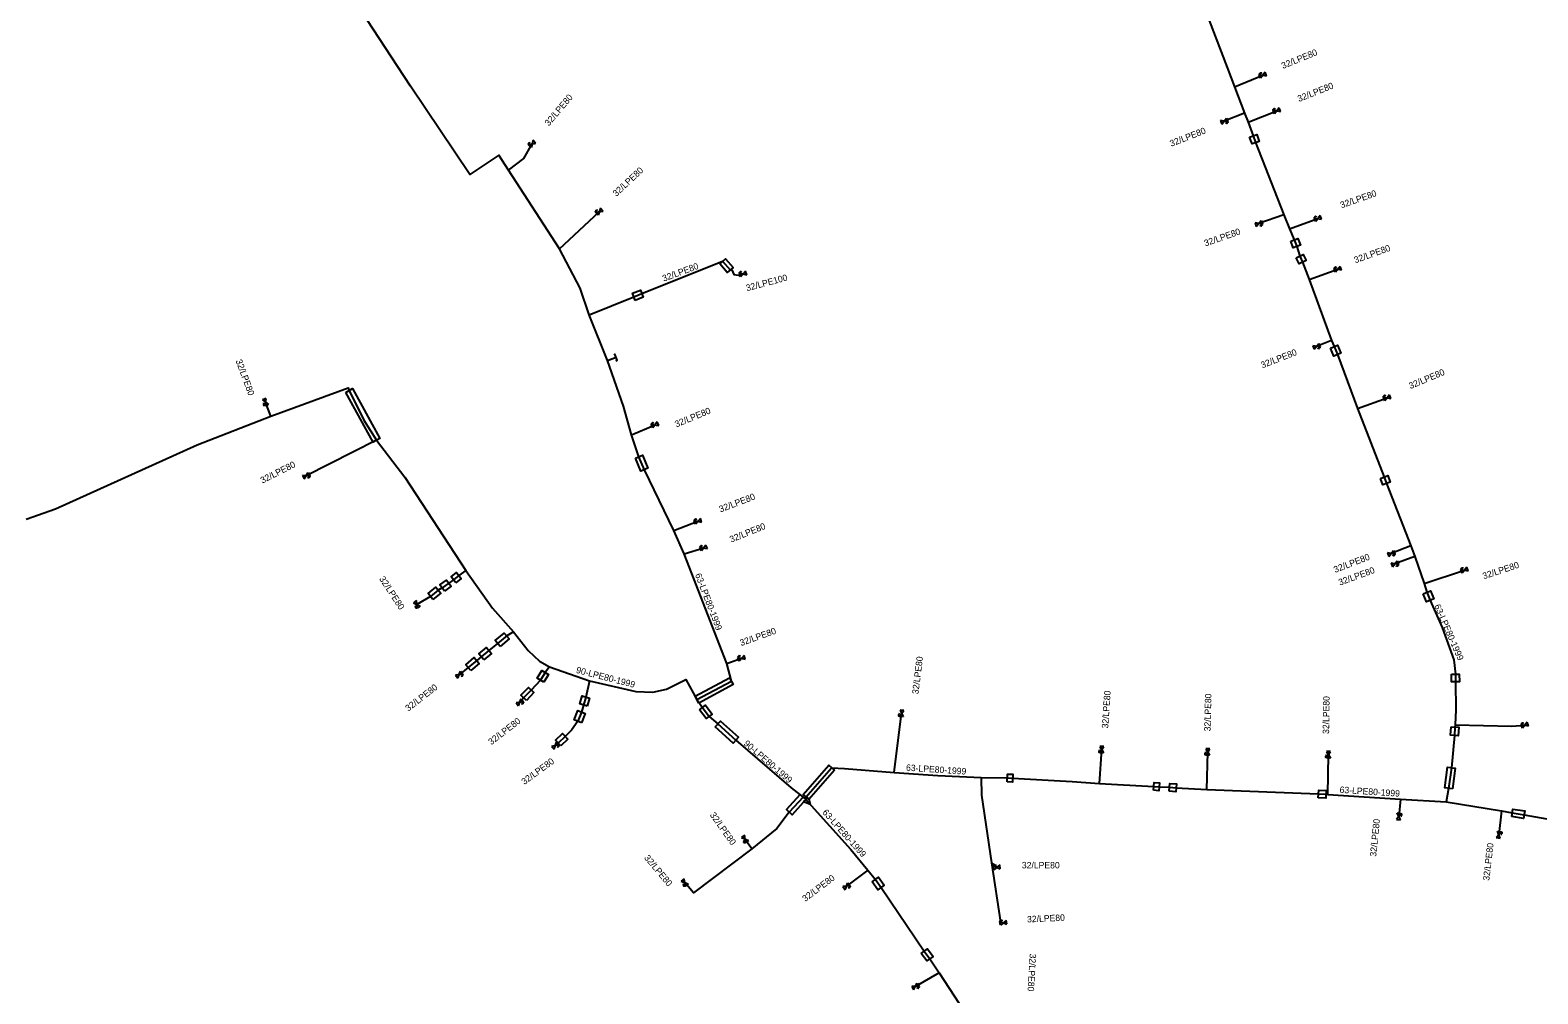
# Model space of a CAD drawing. Extents: x -762927 to -761200, y -1154354 to -1152015.
# Drawn here: x -761676.6 to -761442.6, y -1152557.7 to -1152408 of the extents above; entities that cross this region are included whole.
import ezdxf

# ---------------------------------------------------------------- set-up
doc = ezdxf.new("R2010")
doc.units = 0
for name, color, linetype in [('Vrstva 1', 7, 'Continuous'), ('Vrstva 21', 7, 'Continuous'), ('Vrstva 26', 7, 'Continuous'), ('Vrstva 29', 7, 'Continuous'), ('Vrstva 31', 7, 'Continuous'), ('Vrstva 32', 7, 'Continuous'), ('Vrstva 33', 7, 'Continuous')]:
    doc.layers.add(name, color=color, linetype=linetype)

# ---------------------------------------------------------------- blocks, each defined once
blk = doc.blocks.new('DEC122')
at = {"layer": 'Vrstva 1'}
for p, q in [((-0.5, 0.5), (0.5, 0)), ((-0.5, -0.5), (-0.5, 0.5)), ((0.5, 0), (-0.5, -0.5))]:
    blk.add_line(p, q, dxfattribs=at)
blk = doc.blocks.new('DEC063-SN')
at = {"layer": 'Vrstva 1'}
for p, q in [((-0.5, -0.3), (0.5, 0.3)), ((0.5, -0.3), (-0.5, 0.3)), ((-0.5, 0.3), (-0.5, -0.3)), ((0.5, 0.3), (0.5, -0.3)), ((0.126, -0.318), (0.126, -0.458)), ((0.126, -0.384), (0.206, -0.384)), ((0.206, -0.458), (0.206, -0.318)), ((0.366, -0.458), (0.366, -0.318))]:
    blk.add_line(p, q, dxfattribs=at)
for points in [[(0.246, -0.318), (0.246, -0.418), (0.252, -0.438), (0.264, -0.451), (0.281, -0.458), (0.292, -0.458), (0.309, -0.451), (0.321, -0.438), (0.326, -0.418), (0.326, -0.318)], [(0.366, -0.318), (0.418, -0.318), (0.435, -0.325), (0.441, -0.331), (0.446, -0.344), (0.446, -0.364), (0.441, -0.378), (0.435, -0.384), (0.418, -0.391), (0.366, -0.391)]]:
    blk.add_lwpolyline(points, dxfattribs=at)
blk = doc.blocks.new('DEC130-SN')
at = {"layer": 'Vrstva 1'}
blk.add_lwpolyline([(0.2, 0.5), (0, 0.5), (0, -0.5), (0.2, -0.5)], dxfattribs=at)

msp = doc.modelspace()

# ---------------------------------------------------------------- linework, layer by layer
at = {"layer": 'Vrstva 21'}
for points in [[(-761494.58, -1152404.14), (-761490.85, -1152413.85), (-761489.7, -1152416.84), (-761488.16, -1152420.95), (-761487.6, -1152422.35), (-761486.8, -1152424.45), (-761486.42, -1152425.51), (-761482.06, -1152436.72), (-761481.18, -1152438.87), (-761480.42, -1152440.61), (-761480.05, -1152441.63), (-761479.58, -1152443.13), (-761479.14, -1152444.06), (-761478.09, -1152446.77), (-761474.65, -1152456.23), (-761474.25, -1152457.19), (-761473.73, -1152458.42), (-761470.62, -1152466.8), (-761466.48, -1152477.43), (-761466.1, -1152478.45), (-761462.35, -1152488.13), (-761461.73, -1152489.79), (-761460.26, -1152493.95), (-761459.84, -1152495.33), (-761459.33, -1152496.58), (-761457.49, -1152500.82), (-761455.66, -1152505.82), (-761455.42, -1152508.04), (-761455.4, -1152509.24), (-761455.33, -1152513.56), (-761455.47, -1152515.91), (-761455.49, -1152516.25), (-761455.58, -1152517.56), (-761456.03, -1152522.58), (-761456.47, -1152525.78), (-761456.83, -1152527.87)], [(-761573.13, -1152512), (-761567.78, -1152509.12), (-761568.47, -1152506.37), (-761575.11, -1152489.35), (-761576.69, -1152485.72), (-761581.29, -1152476.29), (-761582.13, -1152474.29), (-761583.3, -1152470.86), (-761584.55, -1152466.45), (-761587.02, -1152459.35), (-761589.85, -1152452.27), (-761591.23, -1152448.11), (-761594.46, -1152442.02), (-761602.36, -1152429.8), (-761603.86, -1152427.44), (-761608.36, -1152430.48), (-761617.59, -1152416.73), (-761625.33, -1152404.89)], [(-761677.24, -1152483.96), (-761672.69, -1152482.38), (-761650.69, -1152472.45), (-761639.27, -1152467.98), (-761627.28, -1152463.58), (-761627.11, -1152464), (-761624.85, -1152468.58), (-761622.86, -1152471.73), (-761618.45, -1152477.46), (-761609.01, -1152491.92), (-761604.85, -1152497.81), (-761601.61, -1152501.48), (-761599.32, -1152504.35), (-761597.57, -1152506.03), (-761596.02, -1152506.9), (-761589.78, -1152509.1), (-761582.63, -1152510.73), (-761579.95, -1152510.84), (-761577.86, -1152510.36), (-761574.83, -1152508.85), (-761573.13, -1152512)], [(-761573.13, -1152512), (-761572.26, -1152513.22), (-761571.23, -1152514.59), (-761569.89, -1152515.77), (-761567.09, -1152518.29), (-761558.48, -1152525.68), (-761556.66, -1152527.12), (-761556.37, -1152527.31)], [(-761556.37, -1152527.31), (-761556.21, -1152527.12), (-761552.23, -1152522.56), (-761550.25, -1152522.69), (-761542.52, -1152523.31), (-761535.75, -1152523.8), (-761529, -1152524.1), (-761524.95, -1152524.15), (-761524.13, -1152524.19), (-761514.88, -1152524.71), (-761510.67, -1152525.03), (-761502.21, -1152525.46), (-761501.38, -1152525.53), (-761499.78, -1152525.61), (-761498.74, -1152525.69), (-761493.99, -1152525.96), (-761476.66, -1152526.63), (-761475.5, -1152526.68), (-761475.2, -1152526.7), (-761463.93, -1152527.44), (-761456.83, -1152527.87)], [(-761556.37, -1152527.31), (-761555.86, -1152527.89)], [(-761555.86, -1152527.89), (-761549.23, -1152535.25), (-761546.63, -1152538.48), (-761545.44, -1152539.91), (-761544.54, -1152541.17), (-761537.84, -1152551.04), (-761536.98, -1152552.22), (-761535.54, -1152554.43), (-761529.45, -1152563.76), (-761525.2, -1152570.86), (-761520.77, -1152578.65), (-761517.06, -1152586.65), (-761515.83, -1152589.42), (-761514.08, -1152593.75), (-761509.53, -1152605.92), (-761503.36, -1152620.97), (-761502.33, -1152623.3), (-761499.83, -1152629.35)], [(-761456.83, -1152527.87), (-761448.25, -1152529.25), (-761446.58, -1152529.57), (-761444.73, -1152529.87), (-761425.09, -1152533.35), (-761412.86, -1152535.83), (-761404.73, -1152537.14), (-761396.67, -1152538.6), (-761395, -1152538.89), (-761392.98, -1152539.26), (-761384.89, -1152540.72), (-761378.87, -1152541.76), (-761369.46, -1152544.68), (-761366.06, -1152546), (-761363.94, -1152546.96), (-761363.78, -1152547.02), (-761358.42, -1152549.62), (-761356.97, -1152550.5), (-761355.51, -1152551.26), (-761353.56, -1152552.55), (-761349.19, -1152555.34), (-761336.19, -1152563.79)]]:
    msp.add_lwpolyline(points, dxfattribs=at)
at = {"layer": 'Vrstva 29'}
for points in [[(-761487.36, -1152424.65), (-761486.23, -1152424.25), (-761485.85, -1152425.31), (-761486.98, -1152425.71)], [(-761480.98, -1152440.81), (-761479.85, -1152440.41), (-761479.48, -1152441.43), (-761480.61, -1152441.83)], [(-761569.6, -1152444.31), (-761568.68, -1152443.53), (-761567.53, -1152444.89), (-761568.45, -1152445.67)], [(-761480.12, -1152443.39), (-761479.04, -1152442.87), (-761478.6, -1152443.8), (-761479.68, -1152444.32)], [(-761582.69, -1152450.01), (-761583.13, -1152448.89), (-761581.91, -1152448.4), (-761581.47, -1152449.52)], [(-761474.8, -1152457.42), (-761473.7, -1152456.96), (-761473.18, -1152458.19), (-761474.28, -1152458.65)], [(-761627.64, -1152464.29), (-761626.58, -1152463.71), (-761622.33, -1152471.44), (-761623.39, -1152472.02)], [(-761582.68, -1152474.52), (-761581.58, -1152474.06), (-761580.74, -1152476.06), (-761581.84, -1152476.52)], [(-761467.04, -1152477.64), (-761465.92, -1152477.22), (-761465.54, -1152478.24), (-761466.66, -1152478.66)], [(-761610.54, -1152493.85), (-761611.28, -1152492.91), (-761610.44, -1152492.24), (-761609.7, -1152493.18)], [(-761614.1, -1152496.46), (-761614.86, -1152495.53), (-761613.66, -1152494.55), (-761612.9, -1152495.48)], [(-761612.29, -1152495.14), (-761613.01, -1152494.18), (-761611.98, -1152493.42), (-761611.26, -1152494.38)], [(-761460.4, -1152495.56), (-761459.28, -1152495.1), (-761458.77, -1152496.35), (-761459.89, -1152496.81)], [(-761603.68, -1152503.73), (-761604.44, -1152502.81), (-761603.03, -1152501.65), (-761602.27, -1152502.57)], [(-761606.2, -1152505.82), (-761606.98, -1152504.9), (-761605.81, -1152503.91), (-761605.03, -1152504.83)], [(-761608.22, -1152507.48), (-761609, -1152506.57), (-761607.7, -1152505.46), (-761606.92, -1152506.36)], [(-761596.9, -1152509.28), (-761597.92, -1152508.66), (-761597.2, -1152507.48), (-761596.18, -1152508.1)], [(-761572.84, -1152512.53), (-761573.41, -1152511.47), (-761568.06, -1152508.59), (-761567.49, -1152509.65)], [(-761456.02, -1152508.05), (-761454.82, -1152508.03), (-761454.8, -1152509.23), (-761456, -1152509.25)], [(-761599.59, -1152512.14), (-761600.46, -1152511.32), (-761599.29, -1152510.09), (-761598.43, -1152510.91)], [(-761590.17, -1152513.01), (-761591.31, -1152512.65), (-761590.93, -1152511.41), (-761589.79, -1152511.77)], [(-761591.06, -1152515.58), (-761592.18, -1152515.14), (-761591.6, -1152513.7), (-761590.48, -1152514.14)], [(-761572.74, -1152513.58), (-761571.78, -1152512.86), (-761570.75, -1152514.23), (-761571.71, -1152514.95)], [(-761570.29, -1152516.22), (-761569.49, -1152515.32), (-761566.69, -1152517.84), (-761567.49, -1152518.74)], [(-761456.09, -1152516.21), (-761454.89, -1152516.29), (-761454.98, -1152517.6), (-761456.18, -1152517.52)], [(-761594.27, -1152519.18), (-761595.09, -1152518.31), (-761593.99, -1152517.27), (-761593.17, -1152518.13)], [(-761555.76, -1152527.51), (-761556.66, -1152526.73), (-761552.68, -1152522.17), (-761551.78, -1152522.95)], [(-761524.98, -1152524.75), (-761524.92, -1152523.55), (-761524.1, -1152523.59), (-761524.16, -1152524.79)], [(-761455.88, -1152525.86), (-761457.06, -1152525.7), (-761456.62, -1152522.5), (-761455.44, -1152522.66)], [(-761502.26, -1152526.06), (-761502.16, -1152524.86), (-761501.33, -1152524.93), (-761501.43, -1152526.13)], [(-761499.83, -1152526.21), (-761499.73, -1152525.01), (-761498.69, -1152525.09), (-761498.79, -1152526.29)], [(-761476.69, -1152527.23), (-761476.63, -1152526.03), (-761475.47, -1152526.08), (-761475.53, -1152527.28)], [(-761557.1, -1152526.72), (-761556.22, -1152527.52), (-761558.36, -1152529.86), (-761559.24, -1152529.05)], [(-761446.68, -1152530.16), (-761446.48, -1152528.98), (-761444.63, -1152529.28), (-761444.83, -1152530.46)], [(-761545.93, -1152540.26), (-761544.95, -1152539.56), (-761544.05, -1152540.82), (-761545.03, -1152541.52)], [(-761538.32, -1152551.39), (-761537.35, -1152550.69), (-761536.49, -1152551.87), (-761537.46, -1152552.57)]]:
    msp.add_lwpolyline(points, close=True, dxfattribs=at)
at = {"layer": 'Vrstva 31'}
for points in [[(-761489.7, -1152416.84), (-761489.69, -1152416.83), (-761485.28, -1152415.03)], [(-761487.6, -1152422.35), (-761483.14, -1152420.58)], [(-761488.16, -1152420.95), (-761491.3, -1152422.17)], [(-761602.36, -1152429.8), (-761599.99, -1152427.96), (-761598.71, -1152425.71)], [(-761594.46, -1152442.02), (-761588.28, -1152436.23)], [(-761482.06, -1152436.72), (-761485.94, -1152438.07)], [(-761481.18, -1152438.87), (-761476.75, -1152437.31)], [(-761589.85, -1152452.27), (-761582.91, -1152449.45), (-761581.69, -1152448.96), (-761569.14, -1152443.92), (-761567.99, -1152445.28), (-761567.7, -1152445.24)], [(-761567.7, -1152445.24), (-761567.41, -1152445.99), (-761566.68, -1152446.09), (-761565.97, -1152445.9)], [(-761478.09, -1152446.77), (-761473.65, -1152445.18)], [(-761474.65, -1152456.23), (-761476.99, -1152457.14)], [(-761587.02, -1152459.35), (-761585.68, -1152458.84)], [(-761470.62, -1152466.8), (-761466.02, -1152465.12)], [(-761639.27, -1152467.98), (-761640.08, -1152465.8)], [(-761583.3, -1152470.86), (-761579.63, -1152469.35)], [(-761622.86, -1152471.73), (-761633.77, -1152477.24)], [(-761576.69, -1152485.72), (-761572.97, -1152484.31)], [(-761575.11, -1152489.35), (-761572.08, -1152488.45)], [(-761462.35, -1152488.13), (-761465.38, -1152489.29)], [(-761461.73, -1152489.79), (-761464.82, -1152490.92)], [(-761609.01, -1152491.92), (-761610.07, -1152492.71), (-761610.91, -1152493.38), (-761611.62, -1152493.9), (-761612.65, -1152494.66), (-761613.28, -1152495.02), (-761614.48, -1152496), (-761616.6, -1152497.21)], [(-761460.26, -1152493.95), (-761454, -1152491.89)], [(-761601.61, -1152501.48), (-761602.65, -1152502.11), (-761604.06, -1152503.27), (-761605.42, -1152504.37), (-761606.59, -1152505.36), (-761607.31, -1152505.91), (-761608.61, -1152507.03), (-761610.02, -1152508.12)], [(-761596.02, -1152506.9), (-761596.69, -1152507.79), (-761597.41, -1152508.97), (-761598.86, -1152510.5), (-761600.03, -1152511.73), (-761600.63, -1152512.42)], [(-761568.47, -1152506.37), (-761566.2, -1152505.56)], [(-761589.78, -1152509.1), (-761590.36, -1152511.59), (-761590.74, -1152512.83), (-761591.04, -1152513.92), (-761591.62, -1152515.36), (-761592.6, -1152516.76), (-761593.58, -1152517.7), (-761594.68, -1152518.75), (-761595.11, -1152519.15)], [(-761542.52, -1152523.31), (-761541.37, -1152514.15)], [(-761455.47, -1152515.91), (-761446.66, -1152516.14), (-761444.63, -1152515.95)], [(-761510.67, -1152525.03), (-761510.31, -1152519.76)], [(-761493.99, -1152525.96), (-761493.84, -1152520.13)], [(-761475.2, -1152526.7), (-761475.11, -1152520.56)], [(-761529, -1152524.1), (-761528.95, -1152526.81), (-761527.42, -1152537.35)], [(-761556.66, -1152527.12), (-761558.8, -1152529.46), (-761560.73, -1152532.01), (-761564.6, -1152535.16)], [(-761463.93, -1152527.44), (-761464.2, -1152530.12)], [(-761448.25, -1152529.25), (-761448.68, -1152532.94)], [(-761564.6, -1152535.16), (-761573.68, -1152541.99), (-761575.03, -1152540.38)], [(-761564.6, -1152535.16), (-761565.67, -1152533.65)], [(-761527.42, -1152537.35), (-761526.01, -1152546.55), (-761525.58, -1152546.66)], [(-761527.42, -1152537.35), (-761526.59, -1152538.03)], [(-761546.63, -1152538.48), (-761549.92, -1152540.97)], [(-761535.54, -1152554.43), (-761539.21, -1152556.53)]]:
    msp.add_lwpolyline(points, dxfattribs=at)

# ---------------------------------------------------------------- block references
at = {"layer": 'Vrstva 26', "rotation": -48.67449996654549}
msp.add_blockref('DEC122', (-761555.86, -1152527.89), dxfattribs=at)
at = {"layer": 'Vrstva 32'}
for p, rotation in [((-761485.28, -1152415.03), -159.45027496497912), ((-761483.14, -1152420.58), -157.82131383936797), ((-761491.3, -1152422.17), 21.232891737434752), ((-761598.71, -1152425.71), -135.57324162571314), ((-761588.28, -1152436.23), -139.38333052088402), ((-761476.75, -1152437.31), -157.71239993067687), ((-761485.94, -1152438.07), 19.184736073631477), ((-761565.97, -1152445.9), -160.73065160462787), ((-761473.65, -1152445.18), -159.1769444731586), ((-761476.99, -1152457.14), 21.25050558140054), ((-761640.08, -1152465.8), -69.61696666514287), ((-761466.02, -1152465.12), -159.46614431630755), ((-761579.63, -1152469.35), -157.67617213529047), ((-761633.77, -1152477.24), 26.795658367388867), ((-761572.97, -1152484.31), -160.73662775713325), ((-761572.08, -1152488.45), -158.7906694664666), ((-761465.38, -1152489.29), 20.94875827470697), ((-761464.82, -1152490.92), 20.087252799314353), ((-761454, -1152491.89), -160.69406114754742), ((-761616.6, -1152497.21), -56.049250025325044), ((-761566.2, -1152505.56), -162.14554165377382), ((-761610.02, -1152508.12), 37.705802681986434), ((-761600.63, -1152512.42), 38.77230566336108), ((-761541.37, -1152514.15), -96.68878611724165), ((-761444.63, -1152515.95), -157.95792773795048), ((-761595.11, -1152519.15), 42.92996948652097), ((-761510.31, -1152519.76), -91.41664449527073), ((-761493.84, -1152520.13), -91.6541055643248), ((-761475.11, -1152520.56), -91.34402219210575), ((-761464.2, -1152530.12), 84.24707495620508), ((-761565.67, -1152533.65), -54.67826101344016), ((-761448.68, -1152532.94), 79.87782226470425), ((-761526.59, -1152538.03), -171.5730305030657), ((-761575.03, -1152540.38), -50.01985269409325), ((-761549.92, -1152540.97), 37.11985279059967), ((-761525.58, -1152546.66), -171.56843619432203), ((-761539.21, -1152556.53), 29.778497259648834)]:
    msp.add_blockref('DEC063-SN', p, dxfattribs=dict(at, rotation=rotation))
at = {"layer": 'Vrstva 33', "rotation": -159.2970998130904}
msp.add_blockref('DEC130-SN', (-761585.68, -1152458.84), dxfattribs=at)

# ---------------------------------------------------------------- texts
at = {"layer": 'Vrstva 21'}
for s, rotation, p in [('63-LPE80-1999', 290.888, (-761573.44, -1152492.59)), ('63-LPE80-1999', 293.459, (-761458.72, -1152497.43)), ('90-LPE80-1999', 345.523, (-761591.95, -1152507.83)), ('90-LPE80-1999', 319.36, (-761565.96, -1152518.95)), ('63-LPE80-1999', 356.194, (-761540.7, -1152523.02)), ('63-LPE80-1999', 356.243, (-761473.41, -1152526.46)), ('63-LPE80-1999', 311.655, (-761553.73, -1152529.56))]:
    msp.add_text(s, height=1, rotation=rotation, dxfattribs=at).set_placement(p)
at = {"layer": 'Vrstva 31'}
for s, rotation, p in [('32/LPE80', 22.204, (-761482.18, -1152414.08)), ('32/LPE80', 21.646, (-761479.69, -1152419.21)), ('32/LPE80', 49.924, (-761596.1, -1152423.01)), ('32/LPE80', 21.233, (-761499.52, -1152426.16)), ('32/LPE80', 43.134, (-761585.64, -1152433.95)), ('32/LPE80', 19.399, (-761473.09, -1152435.72)), ('32/LPE80', 19.185, (-761494.22, -1152441.64)), ('32/LPE80', 19.703, (-761470.94, -1152444.25)), ('32/LPE80', 20.448, (-761578.28, -1152447.11)), ('32/LPE100', 14.931, (-761565.38, -1152448.59)), ('32/LPE80', 21.251, (-761485.39, -1152460.57)), ('32/LPE80', 290.383, (-761644.74, -1152459.38)), ('32/LPE80', 22.795, (-761462.39, -1152463.79)), ('32/LPE80', 22.364, (-761576.33, -1152469.74)), ('32/LPE80', 26.796, (-761640.57, -1152478.46)), ('32/LPE80', 20.758, (-761569.48, -1152482.94)), ('32/LPE80', 21.962, (-761567.82, -1152487.63)), ('32/LPE80', 20.949, (-761474.08, -1152492.32)), ('32/LPE80', 18.215, (-761451.02, -1152493.32)), ('32/LPE80', 303.304, (-761622.49, -1152493.24)), ('32/LPE80', 20.087, (-761473.35, -1152494.3)), ('32/LPE80', 19.638, (-761566.27, -1152503.69)), ('32/LPE80', 82.844, (-761538.76, -1152511.18)), ('32/LPE80', 37.706, (-761617.92, -1152513.87)), ('32/LPE80', 86.092, (-761509.31, -1152516.49)), ('32/LPE80', 88.526, (-761493.42, -1152516.93)), ('32/LPE80', 89.16, (-761475.02, -1152517.33)), ('32/LPE80', 37.594, (-761605.04, -1152519.09)), ('32/LPE80', 36.294, (-761599.91, -1152525.26)), ('32/LPE80', 305.322, (-761571.18, -1152529.91)), ('32/LPE80', 84.247, (-761467.71, -1152536.41)), ('32/LPE80', 83.353, (-761450.16, -1152540.15)), ('32/LPE80', 309.98, (-761581.39, -1152536.59)), ('32/LPE80', 359.857, (-761522.7, -1152538.19)), ('32/LPE80', 37.12, (-761556.31, -1152543.43)), ('32/LPE80', 2.768, (-761521.87, -1152546.6)), ('32/LPE80', 266.608, (-761521.47, -1152551.4))]:
    msp.add_text(s, height=1, rotation=rotation, dxfattribs=at).set_placement(p)

doc.saveas('drawing.dxf')
